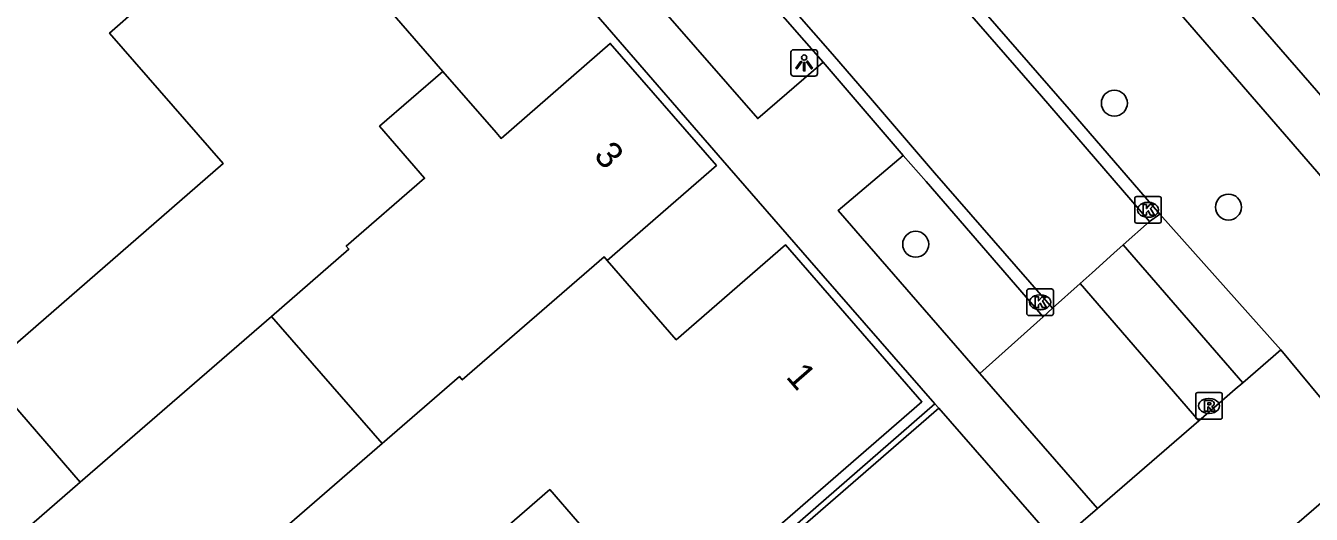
# Model space of a CAD drawing. Extents: x 155888 to 156864, y 383882 to 384671.
# Drawn here: x 156227.53 to 156275.97, y 384092.81 to 384111.22 of the extents above; entities that cross this region are included whole.
import ezdxf

# ---------------------------------------------------------------- set-up
doc = ezdxf.new("R2010")
doc.units = 0
for name, color, linetype in [('IMGEO_Berm_groen', 7, 'Continuous'), ('IMGEO_Boom', 7, 'Continuous'), ('IMGEO_Fietspad_gesloten', 7, 'Continuous'), ('IMGEO_Haag', 7, 'Continuous'), ('IMGEO_Kolk', 7, 'Continuous'), ('IMGEO_Lichtpunt', 7, 'Continuous'), ('IMGEO_Pand', 7, 'Continuous'), ('IMGEO_Pand_nummerreeks', 7, 'Continuous'), ('IMGEO_Rijbaan_lokaal_gesloten', 7, 'Continuous'), ('IMGEO_Rijbaan_lokaal_open', 7, 'Continuous'), ('IMGEO_Rioolput', 7, 'Continuous'), ('IMGEO_Voetpad_open', 7, 'Continuous')]:
    doc.layers.add(name, color=color, linetype=linetype)

msp = doc.modelspace()

# ---------------------------------------------------------------- linework, layer by layer
at = {"layer": 'IMGEO_Berm_groen'}
for points in [[(156270.265, 384104.121), (156274.816, 384099.002)], [(156263.479, 384098.12), (156265.865, 384100.248)]]:
    msp.add_lwpolyline(points, dxfattribs=at)
at = {"layer": 'IMGEO_Boom'}
for centre in [(156268.546, 384108.298), (156272.845, 384104.384), (156261.061, 384102.983)]:
    msp.add_circle(centre, 0.489, dxfattribs=at)
at = {"layer": 'IMGEO_Fietspad_gesloten'}
msp.add_lwpolyline([(156291.359, 384106.231), (156284.254, 384100.056), (156283.954, 384099.797), (156269.896, 384087.691)], dxfattribs=at)
at = {"layer": 'IMGEO_Haag'}
for points in [[(156245.305, 384082.622), (156261.783, 384096.974)], [(156245.422, 384082.489), (156261.927, 384096.809)]]:
    msp.add_lwpolyline(points, dxfattribs=at)
at = {"layer": 'IMGEO_Kolk'}
for p, q in [((156269.312, 384103.855), (156269.312, 384104.707)), ((156269.387, 384104.781), (156270.239, 384104.781)), ((156269.8, 384104.561), (156269.825, 384104.561)), ((156270.313, 384104.707), (156270.313, 384103.855)), ((156270.239, 384103.781), (156269.387, 384103.781)), ((156269.823, 384104.001), (156269.798, 384104.001)), ((156265.247, 384100.374), (156265.247, 384101.226)), ((156265.322, 384101.3), (156266.174, 384101.3)), ((156266.248, 384101.226), (156266.248, 384100.374)), ((156265.735, 384101.08), (156265.76, 384101.08)), ((156266.174, 384100.3), (156265.322, 384100.3)), ((156265.758, 384100.52), (156265.733, 384100.52))]:
    msp.add_line(p, q, dxfattribs=at)
for points in [[(156269.312, 384103.855), (156269.312, 384104.707)], [(156269.387, 384104.781), (156270.239, 384104.781)], [(156270.313, 384104.707), (156270.313, 384103.855)], [(156269.633, 384104.481), (156269.756, 384104.481), (156269.756, 384104.33), (156269.886, 384104.481), (156270.05, 384104.481), (156269.904, 384104.33), (156270.057, 384104.081), (156269.905, 384104.081), (156269.82, 384104.245), (156269.756, 384104.178), (156269.756, 384104.081), (156269.633, 384104.081), (156269.633, 384104.481)], [(156270.239, 384103.781), (156269.387, 384103.781)], [(156265.247, 384100.374), (156265.247, 384101.226)], [(156265.322, 384101.3), (156266.174, 384101.3)], [(156266.248, 384101.226), (156266.248, 384100.374)], [(156265.568, 384101), (156265.691, 384101), (156265.691, 384100.849), (156265.821, 384101), (156265.985, 384101), (156265.839, 384100.849), (156265.992, 384100.6), (156265.84, 384100.6), (156265.755, 384100.764), (156265.691, 384100.697), (156265.691, 384100.6), (156265.568, 384100.6), (156265.568, 384101)], [(156266.174, 384100.3), (156265.322, 384100.3)]]:
    msp.add_lwpolyline(points, dxfattribs=at)
for centre, start, end in [((156269.389, 384104.705), 91.552, 178.448), ((156269.389, 384104.705), 91.552, 178.448), ((156270.237, 384104.705), 1.552, 88.448), ((156270.237, 384104.705), 1.552, 88.448), ((156269.389, 384103.857), 181.552, 268.448), ((156269.389, 384103.857), 181.552, 268.448), ((156270.237, 384103.857), 271.552, 358.448), ((156270.237, 384103.857), 271.552, 358.448), ((156265.324, 384101.224), 91.552, 178.448), ((156265.324, 384101.224), 91.552, 178.448), ((156266.172, 384101.224), 1.552, 88.448), ((156266.172, 384101.224), 1.552, 88.448), ((156265.324, 384100.376), 181.552, 268.448), ((156265.324, 384100.376), 181.552, 268.448), ((156266.172, 384100.376), 271.552, 358.448), ((156266.172, 384100.376), 271.552, 358.448)]:
    msp.add_arc(centre, 0.0765, start, end, dxfattribs=at)
for centre, major_axis, ratio, start_param, end_param in [((156269.799, 384104.281), (-0.387, 0.002), 0.722429, 4.712389, 7.853982), ((156269.824, 384104.281), (-0.39, 0.002), 0.717154, 1.570796, 4.712389), ((156265.734, 384100.8), (-0.387, 0.002), 0.722429, 4.712389, 7.853982), ((156265.759, 384100.8), (-0.39, 0.002), 0.717154, 1.570796, 4.712389)]:
    msp.add_ellipse(centre, major_axis=major_axis, ratio=ratio, start_param=start_param, end_param=end_param, dxfattribs=at)
at = {"layer": 'IMGEO_Lichtpunt'}
for p, q in [((156256.362, 384110.218), (156256.362, 384109.411)), ((156256.362, 384110.218), (156256.362, 384109.411)), ((156257.264, 384110.313), (156256.456, 384110.313)), ((156257.264, 384110.313), (156256.456, 384110.313)), ((156257.358, 384109.411), (156257.358, 384110.218)), ((156257.358, 384109.411), (156257.358, 384110.218)), ((156256.456, 384109.317), (156257.264, 384109.317)), ((156256.456, 384109.317), (156257.264, 384109.317))]:
    msp.add_line(p, q, dxfattribs=at)
for points in [[(156256.736, 384109.882), (156256.775, 384109.854), (156256.587, 384109.592), (156256.549, 384109.619), (156256.736, 384109.882)], [(156256.948, 384109.854), (156256.986, 384109.881), (156257.173, 384109.619), (156257.134, 384109.591), (156256.948, 384109.854)], [(156256.838, 384109.834), (156256.885, 384109.834), (156256.885, 384109.512), (156256.838, 384109.512), (156256.838, 384109.834)]]:
    msp.add_lwpolyline(points, dxfattribs=at)
msp.add_circle((156256.861, 384110.016), 0.0994, dxfattribs=at)
for centre, start, end in [((156256.456, 384110.218), 90, 180), ((156256.456, 384110.218), 90, 180), ((156257.264, 384110.218), 0, 90), ((156257.264, 384110.218), 0, 90), ((156256.456, 384109.411), 180, 270), ((156256.456, 384109.411), 180, 270), ((156257.264, 384109.411), 270, 0), ((156257.264, 384109.411), 270, 360)]:
    msp.add_arc(centre, 0.0946, start, end, dxfattribs=at)
at = {"layer": 'IMGEO_Pand'}
for points in [[(156241.257, 384120.107), (156241.375, 384119.971), (156244.704, 384116.138), (156244.444, 384115.913), (156240.589, 384112.564), (156243.249, 384109.497)], [(156225.97, 384098.203), (156234.965, 384106.021), (156230.69, 384110.939), (156231.808, 384111.909)], [(156243.249, 384109.497), (156245.253, 384107.188), (156245.439, 384106.973), (156249.554, 384110.547), (156253.551, 384105.953), (156249.439, 384102.376)], [(156236.789, 384100.268), (156239.708, 384102.8), (156239.608, 384102.916), (156242.561, 384105.472), (156240.864, 384107.428), (156243.249, 384109.497)], [(156249.439, 384102.376), (156252.039, 384099.387), (156256.151, 384102.964), (156261.293, 384097.054), (156250.026, 384087.273), (156249.817, 384087.515), (156251.448, 384088.93), (156247.275, 384093.741), (156238.225, 384085.892), (156239.798, 384084.078)], [(156249.439, 384102.376), (156249.322, 384102.511), (156243.979, 384097.877), (156243.868, 384098.005), (156240.961, 384095.484)], [(156236.789, 384100.268), (156229.588, 384094.022)], [(156240.961, 384095.484), (156236.789, 384100.268)], [(156225.97, 384098.203), (156229.588, 384094.022)], [(156234.729, 384090.078), (156240.961, 384095.484)], [(156229.588, 384094.022), (156220.6, 384086.227), (156224.76, 384081.431)]]:
    msp.add_lwpolyline(points, dxfattribs=at)
at = {"layer": 'IMGEO_Rijbaan_lokaal_gesloten'}
for points in [[(156269.874, 384103.844), (156265.798, 384108.566), (156259.022, 384116.36), (156235.655, 384143.297)], [(156231.878, 384140.144), (156233.823, 384137.913), (156236.835, 384134.451), (156242.248, 384128.205), (156249.071, 384120.349), (156254.436, 384114.138), (156257.926, 384110.141), (156259.428, 384108.395), (156261.774, 384105.668), (156266.212, 384100.578)], [(156268.884, 384102.961), (156269.874, 384103.844)], [(156267.255, 384101.508), (156267.705, 384101.909), (156268.531, 384102.646), (156268.884, 384102.961)], [(156266.212, 384100.578), (156267.255, 384101.508)]]:
    msp.add_lwpolyline(points, dxfattribs=at)
at = {"layer": 'IMGEO_Rijbaan_lokaal_open'}
for points in [[(156270.265, 384104.121), (156266.847, 384108.071), (156259.86, 384116.097), (156259.369, 384116.661), (156236.378, 384143.165), (156236.004, 384143.601)], [(156254.089, 384113.836), (156257.579, 384109.84)], [(156257.579, 384109.84), (156260.59, 384106.325)], [(156260.59, 384106.325), (156261.455, 384105.344), (156265.865, 384100.248)], [(156269.874, 384103.844), (156270.265, 384104.121)], [(156265.865, 384100.248), (156266.212, 384100.578)]]:
    msp.add_lwpolyline(points, dxfattribs=at)
at = {"layer": 'IMGEO_Rioolput'}
for p, q in [((156271.61, 384096.469), (156271.61, 384097.321)), ((156271.685, 384097.395), (156272.537, 384097.395)), ((156272.611, 384097.321), (156272.611, 384096.469)), ((156272.098, 384097.175), (156272.123, 384097.175)), ((156272.537, 384096.395), (156271.685, 384096.395)), ((156272.121, 384096.615), (156272.096, 384096.615))]:
    msp.add_line(p, q, dxfattribs=at)
for points in [[(156271.61, 384096.469), (156271.61, 384097.321)], [(156271.685, 384097.395), (156272.537, 384097.395)], [(156272.611, 384097.321), (156272.611, 384096.469)], [(156272.199, 384097.093), (156271.947, 384097.095), (156271.947, 384096.695)], [(156271.947, 384096.695), (156272.071, 384096.695), (156272.071, 384096.857), (156272.082, 384096.857)], [(156272.125, 384097.014), (156272.071, 384097.014), (156272.071, 384096.933)], [(156272.071, 384096.933), (156272.123, 384096.933)], [(156272.129, 384096.828), (156272.2, 384096.695), (156272.34, 384096.695), (156272.275, 384096.821)], [(156272.537, 384096.395), (156271.685, 384096.395)]]:
    msp.add_lwpolyline(points, dxfattribs=at)
for centre, radius, start, end in [((156271.687, 384097.319), 0.0765, 91.552, 178.448), ((156271.687, 384097.319), 0.0765, 91.552, 178.448), ((156272.535, 384097.319), 0.0765, 1.552, 88.448), ((156272.535, 384097.319), 0.0765, 1.552, 88.448), ((156272.081, 384096.804), 0.0533, 26.0293, 88.6989), ((156272.107, 384097.122), 0.19, 274.7715, 282.9687), ((156272.131, 384096.918), 0.0964, 77.0061, 93.1865), ((156272.145, 384096.975), 0.0378, 276.6634, 79.6772), ((156272.198, 384096.983), 0.109, 350.3612, 89.416), ((156272.196, 384096.983), 0.112, 277.5842, 350.9817), ((156272.18, 384096.768), 0.108, 29.5134, 73.7905), ((156271.687, 384096.471), 0.0765, 181.552, 268.448), ((156271.687, 384096.471), 0.0765, 181.552, 268.448), ((156272.535, 384096.471), 0.0765, 271.552, 358.448), ((156272.535, 384096.471), 0.0765, 271.552, 358.448)]:
    msp.add_arc(centre, radius, start, end, dxfattribs=at)
for centre, major_axis, ratio, start_param, end_param in [((156272.097, 384096.895), (-0.387, 0.002), 0.722429, 4.712389, 7.853982), ((156272.122, 384096.895), (-0.39, 0.002), 0.717154, 1.570796, 4.712389)]:
    msp.add_ellipse(centre, major_axis=major_axis, ratio=ratio, start_param=start_param, end_param=end_param, dxfattribs=at)
at = {"layer": 'IMGEO_Voetpad_open'}
for points in [[(156240.218, 384147.268), (156267.33, 384115.942), (156277.633, 384104.037), (156281.229, 384099.923)], [(156261.783, 384096.974), (156257.057, 384102.381), (156253.783, 384106.157), (156249.606, 384110.968), (156241.618, 384120.183), (156237.428, 384125.007), (156235.411, 384127.346), (156228.952, 384134.784)], [(156282.76, 384101.221), (156279.529, 384104.91), (156267.335, 384118.935)], [(156254.089, 384113.836), (156251.641, 384111.7), (156255.109, 384107.715), (156257.579, 384109.84)], [(156260.59, 384106.325), (156258.145, 384104.257), (156263.479, 384098.12)], [(156273.38, 384097.76), (156268.884, 384102.961)], [(156271.731, 384096.334), (156267.255, 384101.508)], [(156274.816, 384099.002), (156277.067, 384096.295), (156281.229, 384099.923)], [(156274.816, 384099.002), (156273.38, 384097.76)], [(156267.907, 384093.026), (156263.479, 384098.12)], [(156273.38, 384097.76), (156273.102, 384097.52), (156272.292, 384096.819), (156271.731, 384096.334)], [(156261.783, 384096.974), (156261.927, 384096.809)], [(156261.927, 384096.809), (156266.381, 384091.712)], [(156271.731, 384096.334), (156267.907, 384093.026)], [(156267.907, 384093.026), (156266.381, 384091.712)]]:
    msp.add_lwpolyline(points, dxfattribs=at)

# ---------------------------------------------------------------- texts
at = {"layer": 'IMGEO_Pand_nummerreeks'}
for s, p in [('3', (156248.898, 384106.304)), ('1', (156256.141, 384097.977))]:
    msp.add_text(s, height=1, rotation=311.0236, dxfattribs=at).set_placement(p)

doc.saveas('drawing.dxf')
